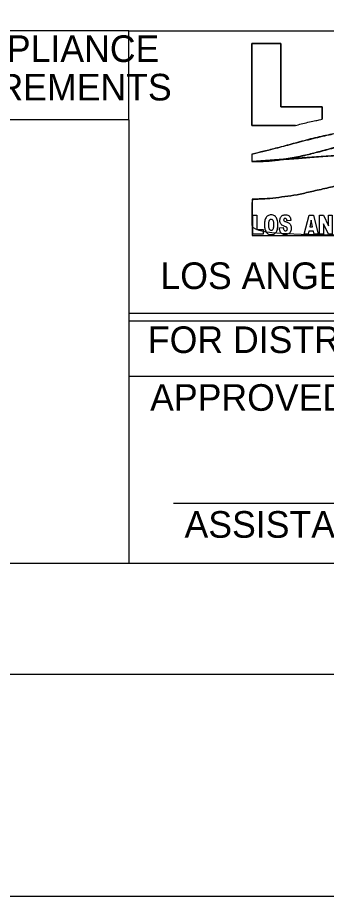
# Model space of a CAD drawing. Extents: x 837 to 1117, y 1316 to 1424.
# Drawn here: x 866.755 to 868.145, y 1398.24 to 1402.2 of the extents above; entities that cross this region are included whole.
import ezdxf

# ---------------------------------------------------------------- set-up
doc = ezdxf.new("R2010")
doc.units = 0
for name, color, linetype in [('0 (Construction)', 7, 'Continuous'), ('BASEMAP', 7, 'Continuous'), ('LLINES', 7, 'Continuous')]:
    doc.layers.add(name, color=color, linetype=linetype)

# ---------------------------------------------------------------- blocks, each defined once
blk = doc.blocks.new('_U1')
for p, q in [((-1.4473, 0.5842), (-1.6244, 0.5842)), ((-1.6244, 0.5842), (-1.6244, 0.0828)), ((-1.4473, 0.1969), (-1.4473, 0.5842)), ((-1.1937, 0.1969), (-1.4473, 0.1969)), ((-1.1937, 0.121), (-1.1937, 0.1969)), ((-1.6244, 0.0828), (-1.3574, 0.0828)), ((-1.6228, -0.0919), (-1.6228, -0.1365)), ((-1.6228, -0.0919), (-1.6228, -0.1365))]:
    blk.add_line(p, q)
blk.add_lwpolyline([(-1.3574, 0.0828), (-1.6244, 0.0828), (-1.6244, 0.5842), (-1.4473, 0.5842), (-1.4473, 0.1969), (-1.1937, 0.1969), (-1.1937, 0.121)])
for points in [[(-1.3574, 0.0828), (-1.3469, 0.0858), (-1.3224, 0.0927), (-1.281, 0.1027), (-1.24, 0.1114), (-1.2103, 0.1177), (-1.1971, 0.1204), (-1.1937, 0.121)], [(-1.3574, 0.0828), (-1.3469, 0.0858), (-1.3224, 0.0927), (-1.281, 0.1027), (-1.24, 0.1114), (-1.2103, 0.1177), (-1.1971, 0.1204), (-1.1937, 0.121)], [(0.862, 0.0351), (0.8144, 0.0286), (0.7268, 0.0166), (0.5878, 0.0117), (0.4579, 0.0164), (0.3153, 0.0281), (0.181, 0.0458), (0.0233, 0.0686), (-0.1285, 0.0898), (-0.3136, 0.1007), (-0.4878, 0.1049), (-0.6455, 0.0979), (-0.7628, 0.0899), (-0.868, 0.0773), (-0.9701, 0.0628), (-1.064, 0.0445), (-1.1579, 0.0251), (-1.2638, 0.0013), (-1.3727, -0.0283), (-1.4702, -0.0549), (-1.5507, -0.0749), (-1.6006, -0.0866), (-1.6228, -0.0919)], [(-1.6228, -0.0919), (-1.5561, -0.0761), (-1.4734, -0.0554), (-1.3817, -0.0308), (-1.2628, 0.0006), (-1.1454, 0.0275), (-1.0649, 0.0442), (-0.9814, 0.06), (-0.8629, 0.0775), (-0.7589, 0.0894), (-0.6661, 0.0962), (-0.5111, 0.1024), (-0.2859, 0.0985), (-0.1443, 0.0891), (0.0432, 0.0657), (0.1706, 0.0476), (0.3298, 0.0278), (0.4464, 0.0181), (0.5981, 0.0133), (0.7189, 0.0181), (0.862, 0.0351), (-1.6228, -0.0919), (0.862, 0.0351)], [(-1.6228, -0.1365), (-1.599, -0.1369), (-1.555, -0.1377), (-1.4818, -0.1315), (-1.3989, -0.1209), (-1.3107, -0.1036), (-1.2241, -0.0808), (-1.1248, -0.0549), (-1.0062, -0.0178), (-0.8775, 0.0183), (-0.754, 0.0461), (-0.6492, 0.0637), (-0.5652, 0.0707), (-0.5035, 0.0751), (-0.4404, 0.0651), (-0.3485, 0.0503), (-0.224, 0.0304), (-0.1005, 0.0101), (0.0189, -0.0072), (0.1408, -0.0203), (0.2859, -0.0336), (0.4577, -0.0356), (0.6419, -0.0205), (0.7839, 0.0038), (0.8533, 0.0316), (0.862, 0.0351)], [(0.862, 0.0351), (0.8359, 0.0249), (0.6443, -0.0172), (0.4416, -0.0333), (0.286, -0.0316), (0.1309, -0.019), (0.0059, -0.0049), (-0.0795, 0.0072), (-0.2275, 0.0308), (-0.3651, 0.053), (-0.4528, 0.067), (-0.5039, 0.0732), (-0.5544, 0.0714), (-0.6368, 0.0638), (-0.7552, 0.0447), (-0.8679, 0.0195), (-1.007, -0.0188), (-1.1422, -0.0589), (-1.2268, -0.0815), (-1.3034, -0.1009), (-1.4037, -0.1206), (-1.4909, -0.1319), (-1.5515, -0.1365), (-1.6228, -0.1365), (0.862, 0.0351), (-1.6228, -0.1365)]]:
    blk.add_open_spline(points, degree=3)
at = {"layer": 'LLINES'}
for p, q in [((-1.6222, -0.3677), (-1.6222, -0.5907)), ((-1.5043, -0.4637), (-1.5043, -0.4637)), ((-1.5053, -0.4912), (-1.5055, -0.4911)), ((-1.3852, -0.4987), (-1.4084, -0.5004)), ((-1.6222, -0.5907), (1.6237, -0.5907)), ((-1.455, -0.5441), (-1.4317, -0.5419))]:
    blk.add_line(p, q, dxfattribs=at)
for points in [[(-1.618, -0.5829), (-1.618, -0.4662), (-1.5939, -0.4662), (-1.5939, -0.4668), (-1.5939, -0.5537), (-1.5541, -0.5537), (-1.5541, -0.5829), (-1.618, -0.5829)], [(-1.2427, -0.583), (-1.2467, -0.5634), (-1.2747, -0.5634), (-1.279, -0.5827), (-1.304, -0.5828), (-1.2739, -0.466), (-1.2739, -0.4656), (-1.2739, -0.466), (-1.2472, -0.466), (-1.2171, -0.583), (-1.2427, -0.583)], [(-1.1555, -0.583), (-1.1856, -0.5188), (-1.1856, -0.5828), (-1.209, -0.5828), (-1.209, -0.4658), (-1.209, -0.4658), (-1.209, -0.4658), (-1.1861, -0.4656), (-1.1559, -0.5302), (-1.1559, -0.466), (-1.1327, -0.466), (-1.1327, -0.583), (-1.1555, -0.583)]]:
    blk.add_lwpolyline(points, dxfattribs=at)
blk.add_lwpolyline([(-1.2695, -0.5381), (-1.2519, -0.5381), (-1.2609, -0.4966)], close=True, dxfattribs=at)
for points in [[(1.6237, -0.1737), (1.5983, -0.1738), (1.5491, -0.1739), (1.4571, -0.1888), (1.3294, -0.2187), (1.1518, -0.2794), (0.9561, -0.3425), (0.7506, -0.3705), (0.5779, -0.3926), (0.4178, -0.4012), (0.2906, -0.4008), (0.1563, -0.396), (0.0001, -0.3778), (-0.1826, -0.346), (-0.3534, -0.3102), (-0.4923, -0.2765), (-0.6042, -0.249), (-0.6984, -0.2398), (-0.7699, -0.2373), (-0.8303, -0.2385), (-0.9006, -0.2439), (-0.9843, -0.2576), (-1.0837, -0.2798), (-1.1773, -0.3031), (-1.27, -0.3237), (-1.3481, -0.3418), (-1.4221, -0.3516), (-1.497, -0.3622), (-1.5633, -0.3666), (-1.6073, -0.3674), (-1.6222, -0.3677), (-1.6222, -0.442), (-1.6222, -0.5164), (-1.6222, -0.5907), (-0.5402, -0.5907), (0.5418, -0.5907), (1.6237, -0.5907), (1.6237, -0.4517), (1.6237, -0.3127), (1.6237, -0.1737)], [(1.6237, -0.1737), (1.5983, -0.1738), (1.5491, -0.1739), (1.4571, -0.1888), (1.3294, -0.2187), (1.1518, -0.2794), (0.9561, -0.3425), (0.7506, -0.3705), (0.5779, -0.3926), (0.4178, -0.4012), (0.2906, -0.4008), (0.1563, -0.396), (0.0001, -0.3778), (-0.1826, -0.346), (-0.3534, -0.3102), (-0.4923, -0.2765), (-0.6042, -0.249), (-0.6984, -0.2398), (-0.7699, -0.2373), (-0.8303, -0.2385), (-0.9006, -0.2439), (-0.9843, -0.2576), (-1.0837, -0.2798), (-1.1773, -0.3031), (-1.27, -0.3237), (-1.3481, -0.3418), (-1.4221, -0.3516), (-1.497, -0.3622), (-1.5633, -0.3666), (-1.6073, -0.3674), (-1.6222, -0.3677)], [(-1.5043, -0.4637), (-1.5015, -0.464), (-1.4941, -0.4646), (-1.484, -0.469), (-1.4758, -0.4774), (-1.4698, -0.4875), (-1.4658, -0.5005), (-1.4638, -0.5164), (-1.4639, -0.5321), (-1.4656, -0.5462), (-1.4686, -0.5578), (-1.4735, -0.568), (-1.4806, -0.5765), (-1.4894, -0.5824), (-1.4989, -0.5848), (-1.5082, -0.5847), (-1.5173, -0.5835), (-1.5255, -0.5798), (-1.5332, -0.5735), (-1.5388, -0.5644), (-1.544, -0.5524), (-1.5462, -0.5397), (-1.5469, -0.5282), (-1.5468, -0.5189), (-1.5459, -0.508), (-1.5439, -0.4964), (-1.5394, -0.4848), (-1.5338, -0.4761), (-1.5265, -0.4695), (-1.5166, -0.4644), (-1.5089, -0.4639), (-1.5043, -0.4637)], [(-1.4317, -0.5419), (-1.4316, -0.5434), (-1.431, -0.5479), (-1.4292, -0.5544), (-1.4246, -0.5601), (-1.4185, -0.5625), (-1.412, -0.5611), (-1.4074, -0.5563), (-1.4061, -0.5499), (-1.4074, -0.5429), (-1.4131, -0.5377), (-1.4214, -0.5353), (-1.4306, -0.5318), (-1.4398, -0.5269), (-1.4469, -0.5192), (-1.451, -0.5099), (-1.4525, -0.4993), (-1.4516, -0.4897), (-1.4488, -0.4807), (-1.4444, -0.4736), (-1.4384, -0.468), (-1.4309, -0.465), (-1.4227, -0.464), (-1.4134, -0.4636), (-1.4043, -0.4656), (-1.3957, -0.4703), (-1.3895, -0.4782), (-1.3862, -0.4882), (-1.3855, -0.4952), (-1.3852, -0.4987)], [(-1.5055, -0.4911), (-1.507, -0.4912), (-1.5101, -0.4914), (-1.5139, -0.4942), (-1.5175, -0.498), (-1.5196, -0.5033), (-1.5212, -0.5096), (-1.5219, -0.5167), (-1.522, -0.5238), (-1.5221, -0.5304), (-1.5214, -0.5365), (-1.5205, -0.5427), (-1.5186, -0.5489), (-1.5151, -0.554), (-1.5103, -0.5573), (-1.5053, -0.5579), (-1.5, -0.5573), (-1.4947, -0.5534), (-1.4911, -0.5467), (-1.4893, -0.538), (-1.4888, -0.5286), (-1.4886, -0.5186), (-1.4894, -0.5093), (-1.4915, -0.5015), (-1.4951, -0.4955), (-1.4999, -0.4918), (-1.5037, -0.4913), (-1.5053, -0.4912)], [(-1.4084, -0.5004), (-1.4087, -0.4985), (-1.4092, -0.4945), (-1.4114, -0.4893), (-1.4159, -0.4864), (-1.4207, -0.4853), (-1.4255, -0.4864), (-1.4286, -0.49), (-1.4298, -0.4948), (-1.4279, -0.5001), (-1.4217, -0.5039), (-1.4132, -0.5059), (-1.4038, -0.5098), (-1.395, -0.5144), (-1.3884, -0.5215), (-1.3842, -0.5302), (-1.3821, -0.5398), (-1.3824, -0.551), (-1.3848, -0.5619), (-1.3897, -0.5716), (-1.3963, -0.5787), (-1.4046, -0.5833), (-1.4138, -0.5849), (-1.4226, -0.5849), (-1.4309, -0.5835), (-1.4384, -0.5807), (-1.4451, -0.5756), (-1.4499, -0.5677), (-1.453, -0.5584), (-1.4548, -0.5504), (-1.4549, -0.5456), (-1.455, -0.5441)]]:
    blk.add_open_spline(points, degree=3, dxfattribs=at)

msp = doc.modelspace()

# ---------------------------------------------------------------- linework, layer by layer
at = {"layer": '0 (Construction)'}
msp.add_lwpolyline([(841.77, 1422.24), (877.77, 1422.24), (877.77, 1398.24), (841.77, 1398.24)], close=True, dxfattribs=at)
at = {"layer": 'BASEMAP'}
for p, q in [((870.7551, 1400.8665), (867.2551, 1400.8665)), ((870.7551, 1400.8323), (867.2551, 1400.8323)), ((870.7551, 1400.5823), (867.2551, 1400.5823)), ((869.4565, 1400.0104), (867.4565, 1400.0104)), ((876.52, 1399.74), (843.52, 1399.74)), ((877.02, 1399.24), (843.02, 1399.24))]:
    msp.add_line(p, q, dxfattribs=at)
for points in [[(867.2552, 1402.14), (865.2552, 1402.14)], [(867.2552, 1402.14), (876.52, 1402.14)], [(867.2552, 1401.74), (867.2552, 1402.14)], [(867.2552, 1401.74), (865.2552, 1401.74)], [(867.2552, 1401.74), (867.2552, 1399.74)]]:
    msp.add_lwpolyline(points, dxfattribs=at)

# ---------------------------------------------------------------- block references
at = {"xscale": 0.7363891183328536, "yscale": 0.7363891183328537}
msp.add_blockref('_U1', (869.0051, 1401.653), dxfattribs=at)

# ---------------------------------------------------------------- texts
at = {"layer": 'BASEMAP'}
for s, p in [('REVIEWED FOR COMPLIANCE', (865.048, 1402.0002)), ('WITH DISTRICT REQUIREMENTS', (864.9168, 1401.8269))]:
    msp.add_text(s, height=0.12, dxfattribs=at).set_placement(p)
at = {"layer": 'LLINES'}
for s, p in [('LOS ANGELES COUNTY PUBLIC WORKS', (867.3978, 1400.9771)), ('FOR DISTRICT USE ONLY', (867.3413, 1400.6888)), ('APPROVED BY:', (867.3514, 1400.4284)), ('ASSISTANT DEPUTY DIRECTOR', (867.5063, 1399.8563))]:
    msp.add_text(s, height=0.12, dxfattribs=at).set_placement(p)

doc.saveas('drawing.dxf')
